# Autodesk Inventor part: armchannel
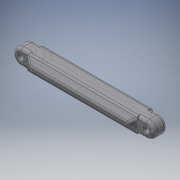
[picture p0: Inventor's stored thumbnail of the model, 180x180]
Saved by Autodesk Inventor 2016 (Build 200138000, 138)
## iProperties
Created: 2015-05
Part Number: armchannel
Material: Generic
Document SubType Name: Modeling
Designer: Brent
Density: 1 g/cm^3
Appearance: Default
Author: Brent
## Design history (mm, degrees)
sketch "Sketch1"
  geometry: L1 (5.563, 12.383)-(8.39, 12.383) reference; L2 (5.716, 10.859)-(5.716, 11.43) reference; L3 (-4.211, 7.112)-(1.474, 7.112) reference; L4 (-4.211, 0.127)-(-4.211, 7.112) reference; L5 (-3.853, 0.127)-(-4.211, 0.127) reference; L6 (-3.853, 4.508)-(-3.853, 0.127) reference; L7 (-1.02, 4.508)-(-3.853, 4.508) reference; L8 (2.803, 0.635)-(2.803, 0.762) reference; L9 (8.39, 0.635)-(2.803, 0.635) reference; L10 (14.105, 6.668)-(14.105, 6.35) reference; L11 (8.39, 13.018)-(5.563, 13.018) reference; L12 (2.803, 0)-(8.39, 0) reference; C1 r 2.159 at (8.39, 6.509) reference; C2 r 1.515 at (8.39, 6.509); C3 r 6.429 at (8.39, 6.509); 6 further points
  constraints: 2 centre point, 2 coincident, 1 other
extrude "Extrusion1" new body sketch "Sketch1" distance "d0" = 10.668; taper "d1" = 0 deg
sketch "Sketch2"
  geometry: L1 (-0.036, 6.429)-(-101.636, 6.429); L2 (-101.636, -6.429)-(-0.036, -6.429); L3 (-0.036, -6.429)-(-0.036, -6.429); C1 r 2.159 at (0, 0) reference; C2 r 2.159 at (-101.636, 0); A1 r 6.429 centre (0, 0) between (-0.036, 6.429) and (-0.036, -6.429) reference; A2 r 6.429 centre (-101.636, 0) between (-101.636, 6.429) and (-101.636, -6.429); 2 further points
  constraints: 6 end point, 4 point on circle, 2 centre point, 1 coincident, 1 horizontal, 1 parallel, 2 other
extrude "Extrusion2" join sketch "Sketch2" distance "d3" = 10.668; taper "d4" = 0 deg
sketch "Sketch3"
  geometry: L1 (101.6, 0)-(0, 0) reference; L2 (101.6, 0)-(101.6, 10.668) reference; L3 (0, 10.668)-(101.6, 10.668) reference; L4 (0, 0)-(0, 10.668) reference; L5 (96.657, 7.798)-(4.943, 7.798); L6 (4.943, 7.798)-(4.943, 2.87); L7 (4.943, 2.87)-(96.657, 2.87); L8 (96.657, 2.87)-(96.657, 7.798); L9 (96.657, 7.798)-(4.943, 2.87); L10 (4.943, 7.798)-(96.657, 2.87); 2 further points
  constraints: 12 end point, 2 midpoint, 2 parallel, 1 horizontal, 1 perpendicular
extrude "Extrusion3" cut sketch "Sketch3" distance "d5" = 9.9695; taper "d6" = 0 deg
sketch "Sketch4"
  geometry: L1 (4.943, 7.798)-(96.657, 7.798) reference; L2 (4.943, 2.87)-(4.943, 7.798) reference; L3 (96.657, 2.87)-(4.943, 2.87) reference; L4 (96.657, 7.798)-(96.657, 2.87) reference; L5 (96.657, 2.87)-(4.943, 2.87) reference; L6 (4.943, 7.798)-(96.657, 7.798) reference; L7 (84.804, 2.87)-(17.15, 2.87); L8 (17.15, 2.87)-(17.15, 7.798); L9 (17.15, 7.798)-(84.804, 7.798); L10 (84.804, 7.798)-(84.804, 2.87); 1 further point
  constraints: 8 end point, 2 parallel, 2 point on line, 1 horizontal, 1 perpendicular
extrude "Extrusion4" join sketch "Sketch4" distance "d7" = 2.7305; taper "d8" = 0 deg
fillet "Fillet1" dims "d9" = 12.7
fillet "Fillet2" dims "d10" = 12.7
chamfer "Chamfer1" distance "d11" = 1.5875; stored, may be unused: second distance "d12" = 3.175, angle "d13" = 45 deg
sketch "Sketch5"
  geometry: L1 (-8.426, 12.938)-(-110.026, 12.938) reference; L2 (-110.026, 0.08)-(-8.426, 0.08) reference; L3 (-8.426, 0.08)-(-8.426, 0.08) reference; L4 (-105.74, 12.938)-(-12.676, 12.938); L5 (-110.026, 0.08)-(-8.426, 0.08) reference; L6 (-12.676, 0.08)-(-105.74, 0.08); C1 r 2.159 at (-110.026, 6.509) reference; C2 r 2.159 at (-8.39, 6.509) reference; A1 r 6.429 centre (-8.39, 6.509) between (-8.426, 0.08) and (-8.426, 12.938) reference; A2 r 6.429 centre (-110.026, 6.509) between (-110.026, 12.938) and (-110.026, 0.08) reference; A3 r 7.727 centre (-8.39, 6.509) between (-12.676, 12.938) and (-12.676, 0.08); A4 r 7.727 centre (-110.026, 6.509) between (-105.74, 0.08) and (-105.74, 12.938); 1 further point
  constraints: 4 end point, 4 point on circle, 4 point on line, 2 centre point, 2 coincident
extrude "Extrusion5" join sketch "Sketch5" distance "d14" = 4.318; taper "d15" = 0 deg
sketch "Sketch6"
  geometry: L1 (12.676, 12.938)-(105.74, 12.938) reference; L2 (105.74, 0.08)-(12.676, 0.08) reference; A1 r 7.727 centre (110.026, 6.509) between (105.74, 12.938) and (105.74, 0.08) reference; A2 r 7.727 centre (8.39, 6.509) between (12.676, 0.08) and (12.676, 12.938) reference; 1 further point
extrude "Extrusion6" join sketch "Sketch6" distance "d16" = 4.318; taper "d17" = 0 deg
fillet "Fillet3" dims "d18" = 2.54
fillet "Fillet4" dims "d19" = 2.5146
chamfer "Chamfer2" distance "d20" = 2.8575; stored, may be unused: second distance "d21" = 3.175, angle "d22" = 45 deg
chamfer "Chamfer3" distance "d23" = 4.445; stored, may be unused: second distance "d24" = 3.175, angle "d25" = 45 deg
fillet "Fillet5" dims "d26" = 2.5146
chamfer "Chamfer4" distance "d27" = 0.508; stored, may be unused: second distance "d28" = 3.175, angle "d29" = 45 deg
chamfer "Chamfer5" distance "d30" = 0.508; stored, may be unused: second distance "d31" = 3.175, angle "d32" = 45 deg
body "Solid1"
node "Reference1"
node "Reference2"
node "Reference3"
node "Reference4"
node "Reference5"
node "Reference6"
node "Projected Loop1"
node "Projected Loop2"
node "Projected Loop3"
node "Projected Loop4"
node "Projected Loop5"
